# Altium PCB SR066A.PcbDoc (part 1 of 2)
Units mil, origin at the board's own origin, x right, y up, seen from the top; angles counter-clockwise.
Board outline 2000 x 2000 mil, 4 copper layers (Top Layer, Signal Layer 1, Signal Layer 2, Bottom Layer), stack 60.434 mil thick; 64 components, 14 nets, 91 pads, 124 vias.
Unrouted connection lines stored in the file: 2.
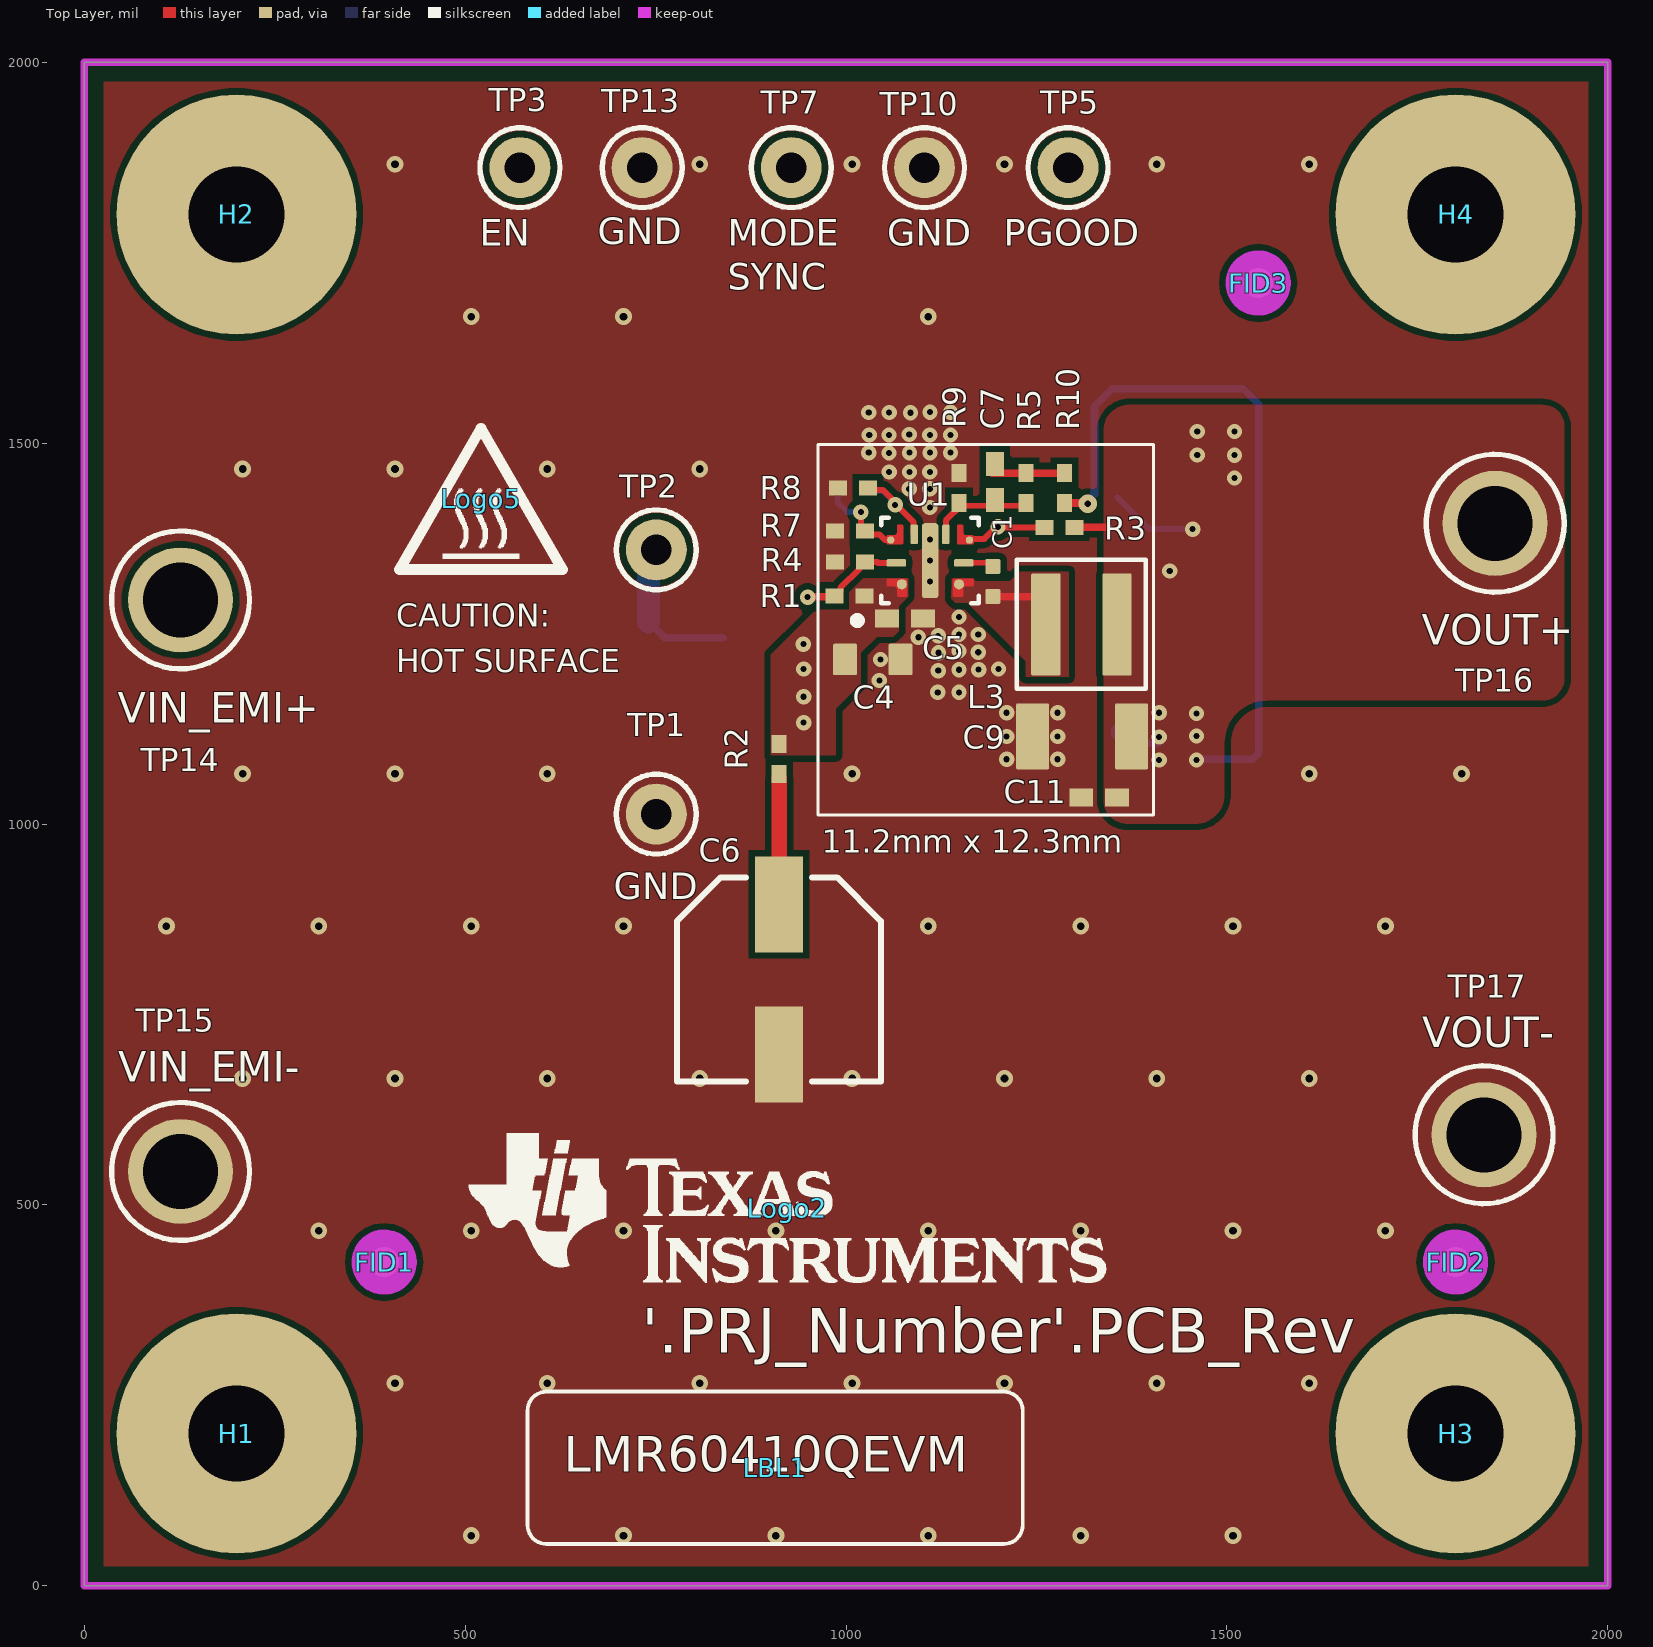
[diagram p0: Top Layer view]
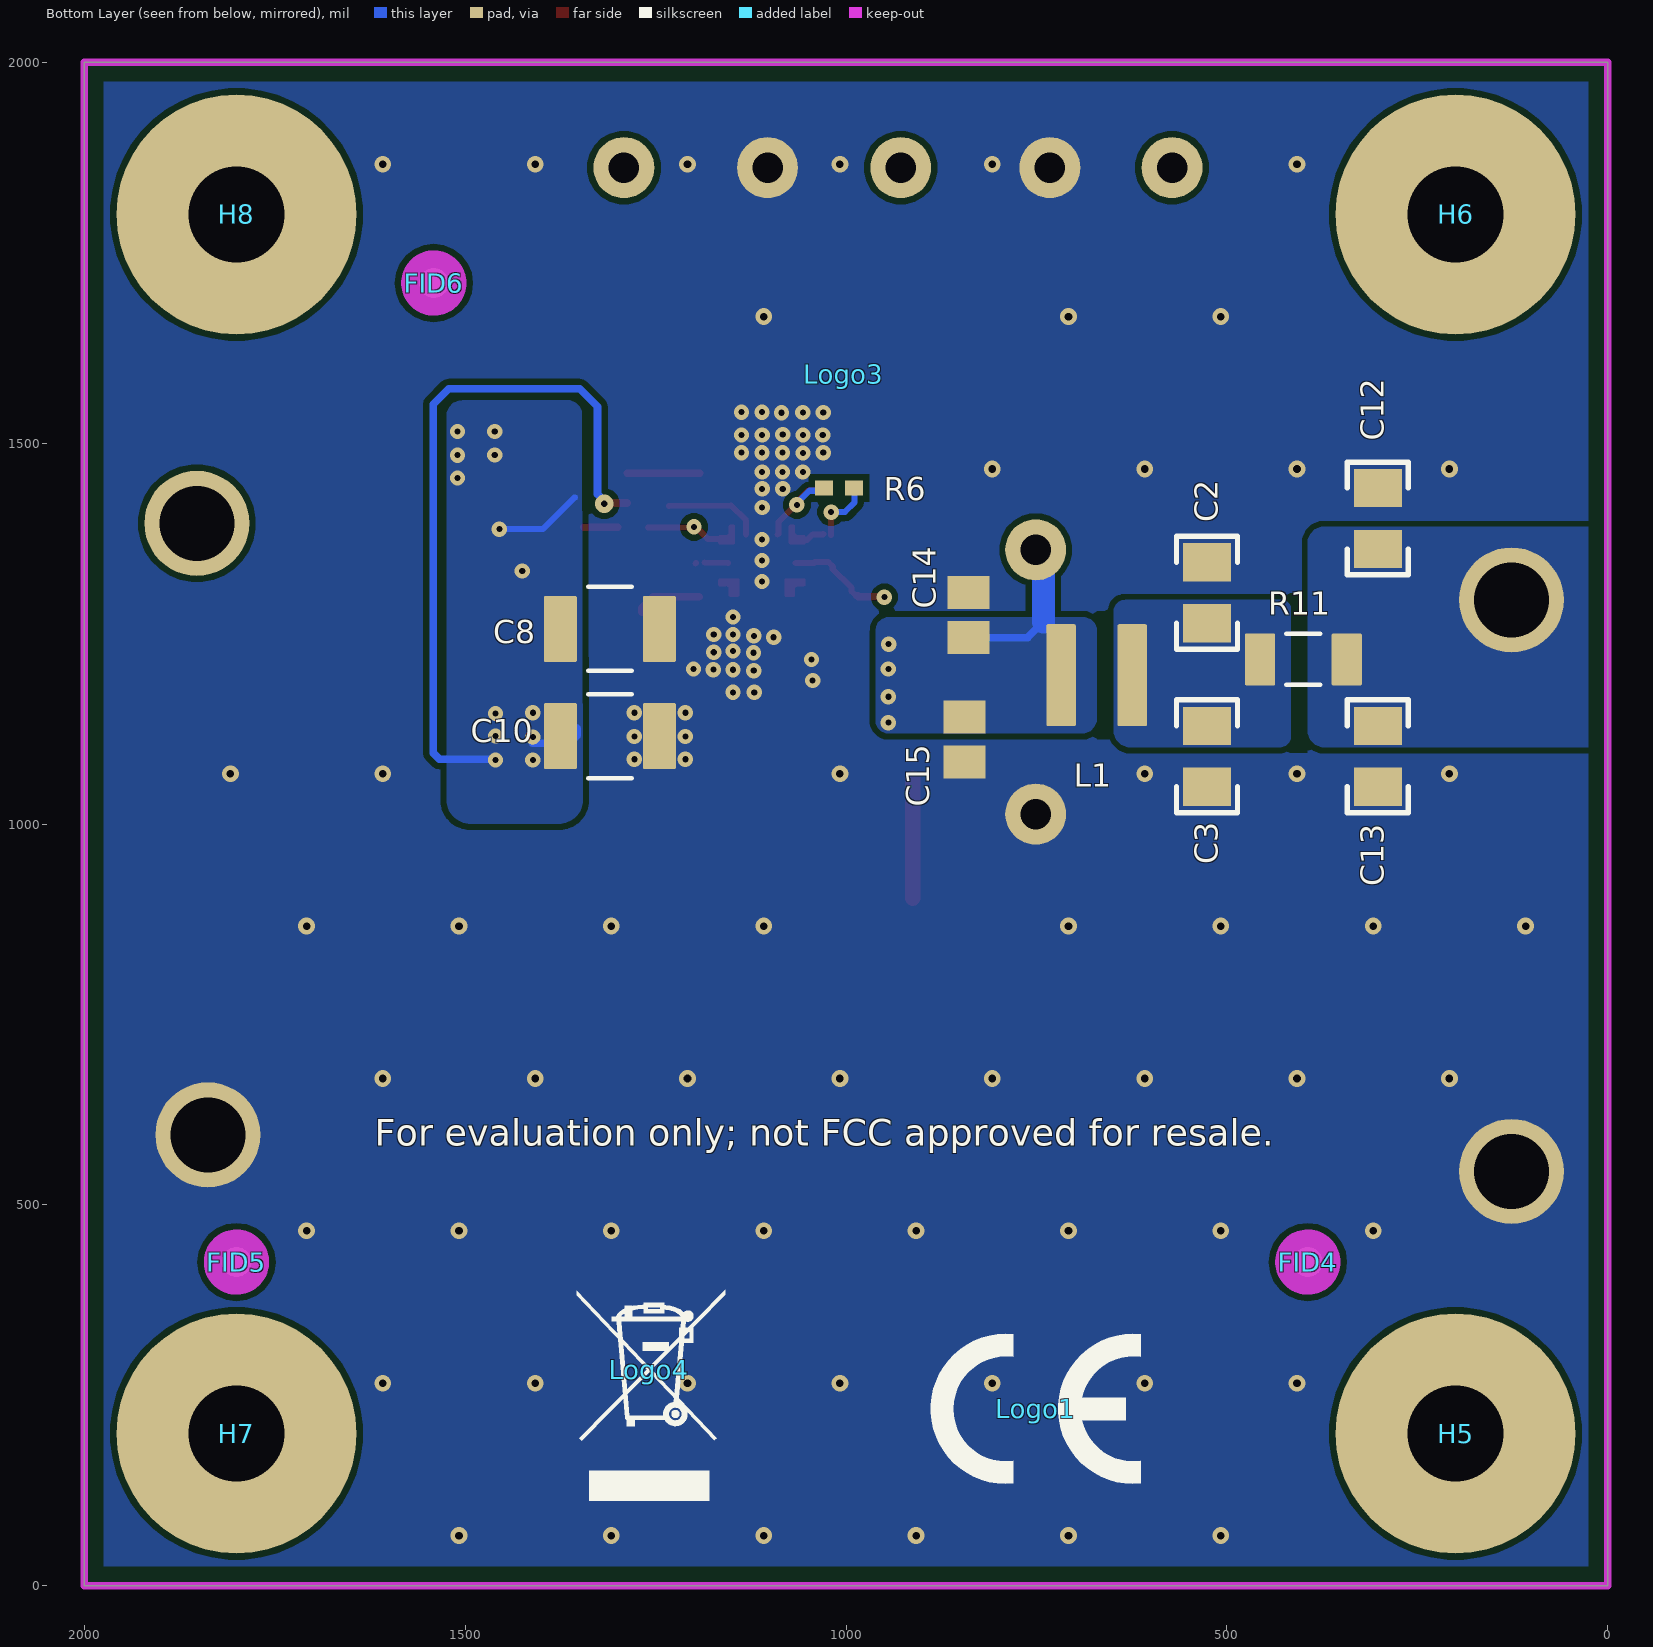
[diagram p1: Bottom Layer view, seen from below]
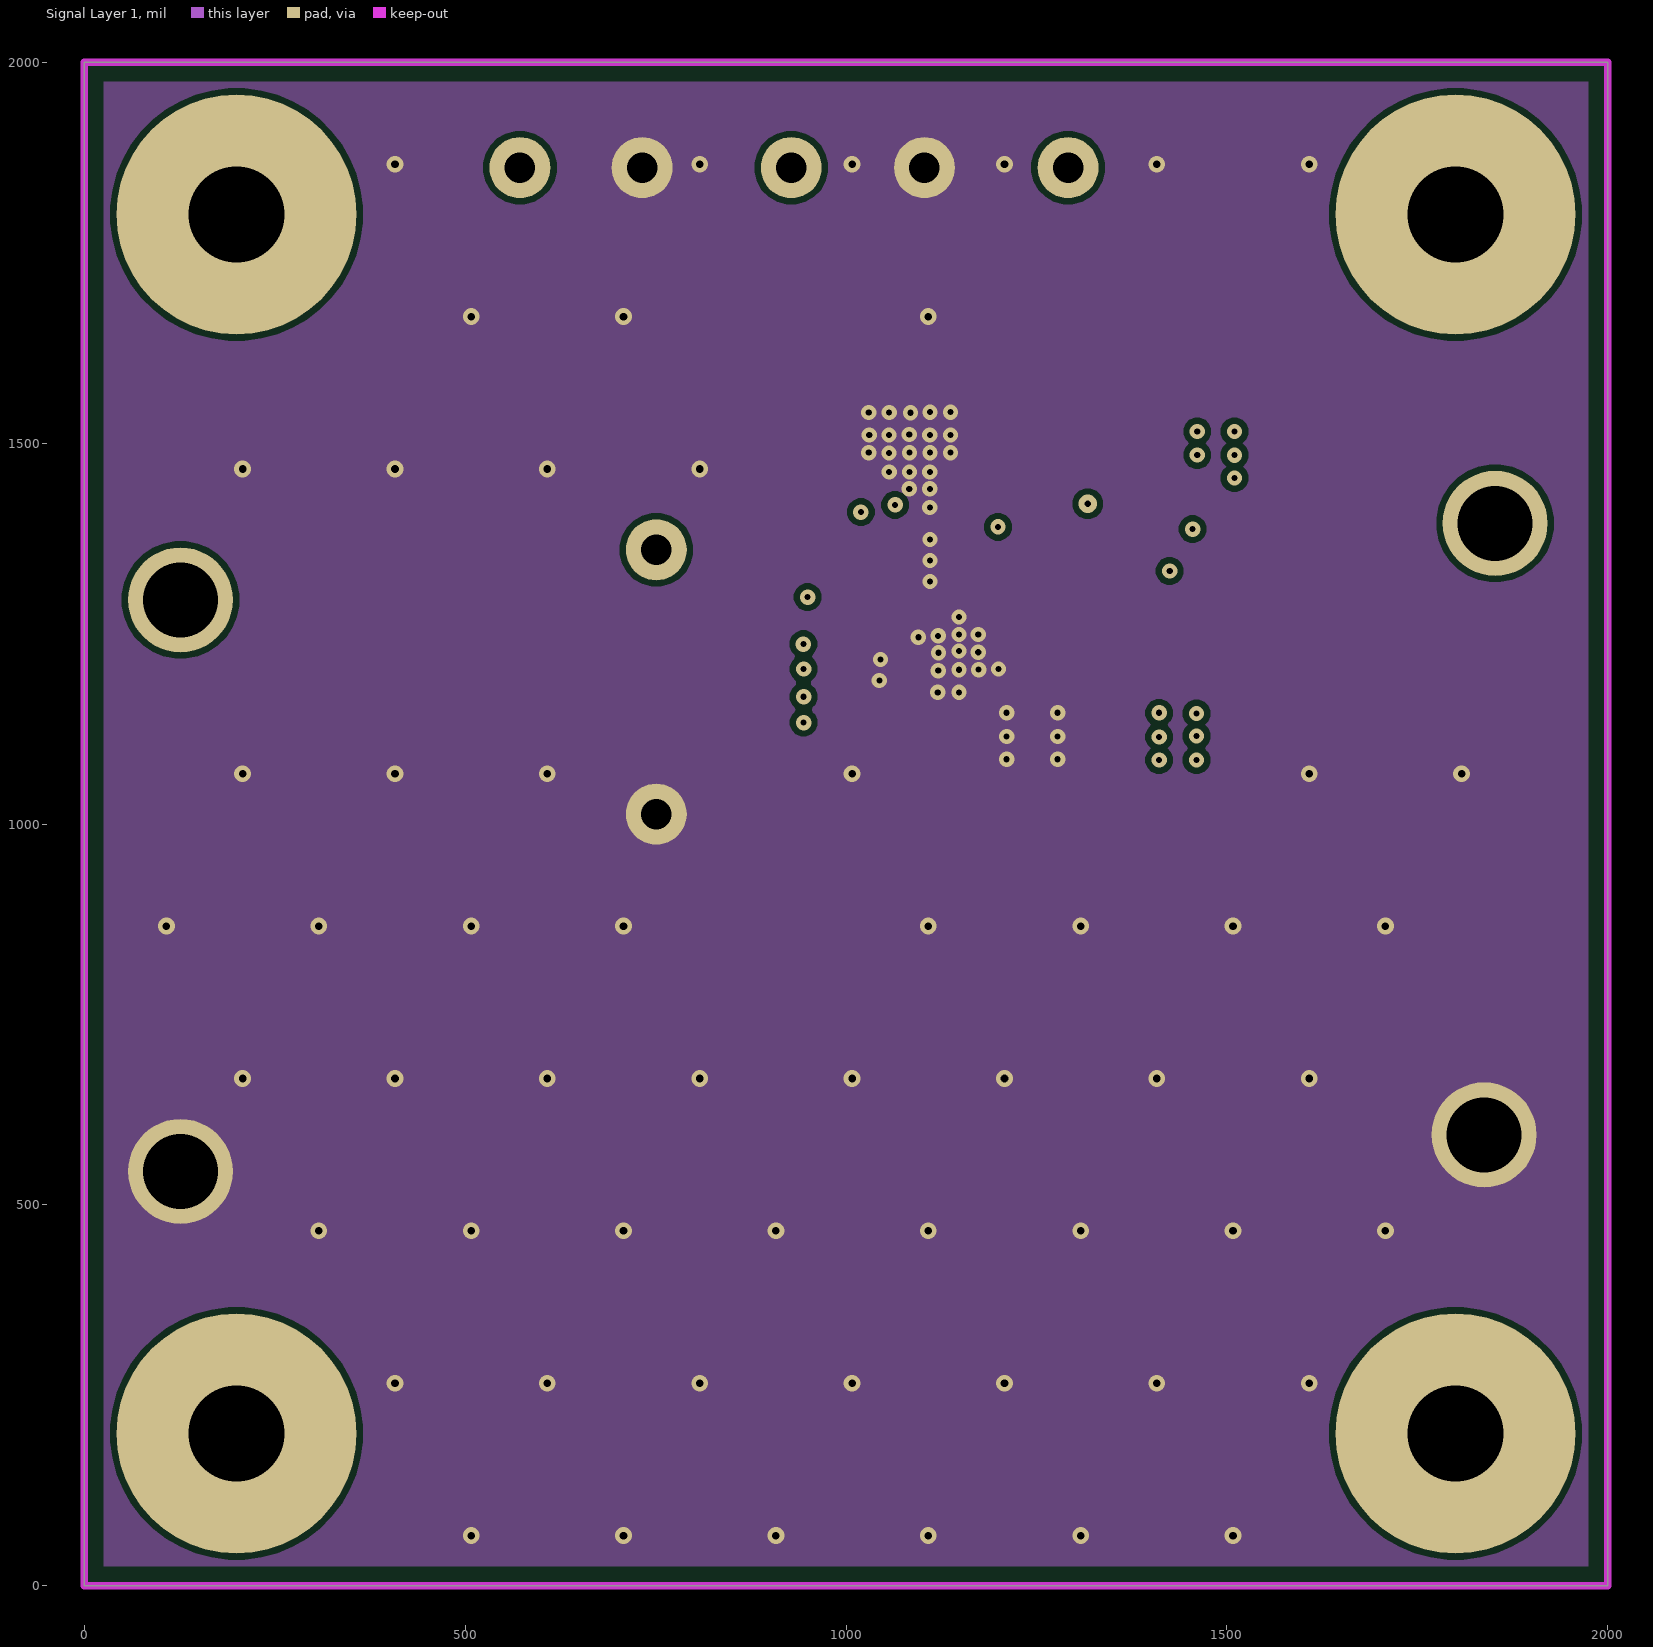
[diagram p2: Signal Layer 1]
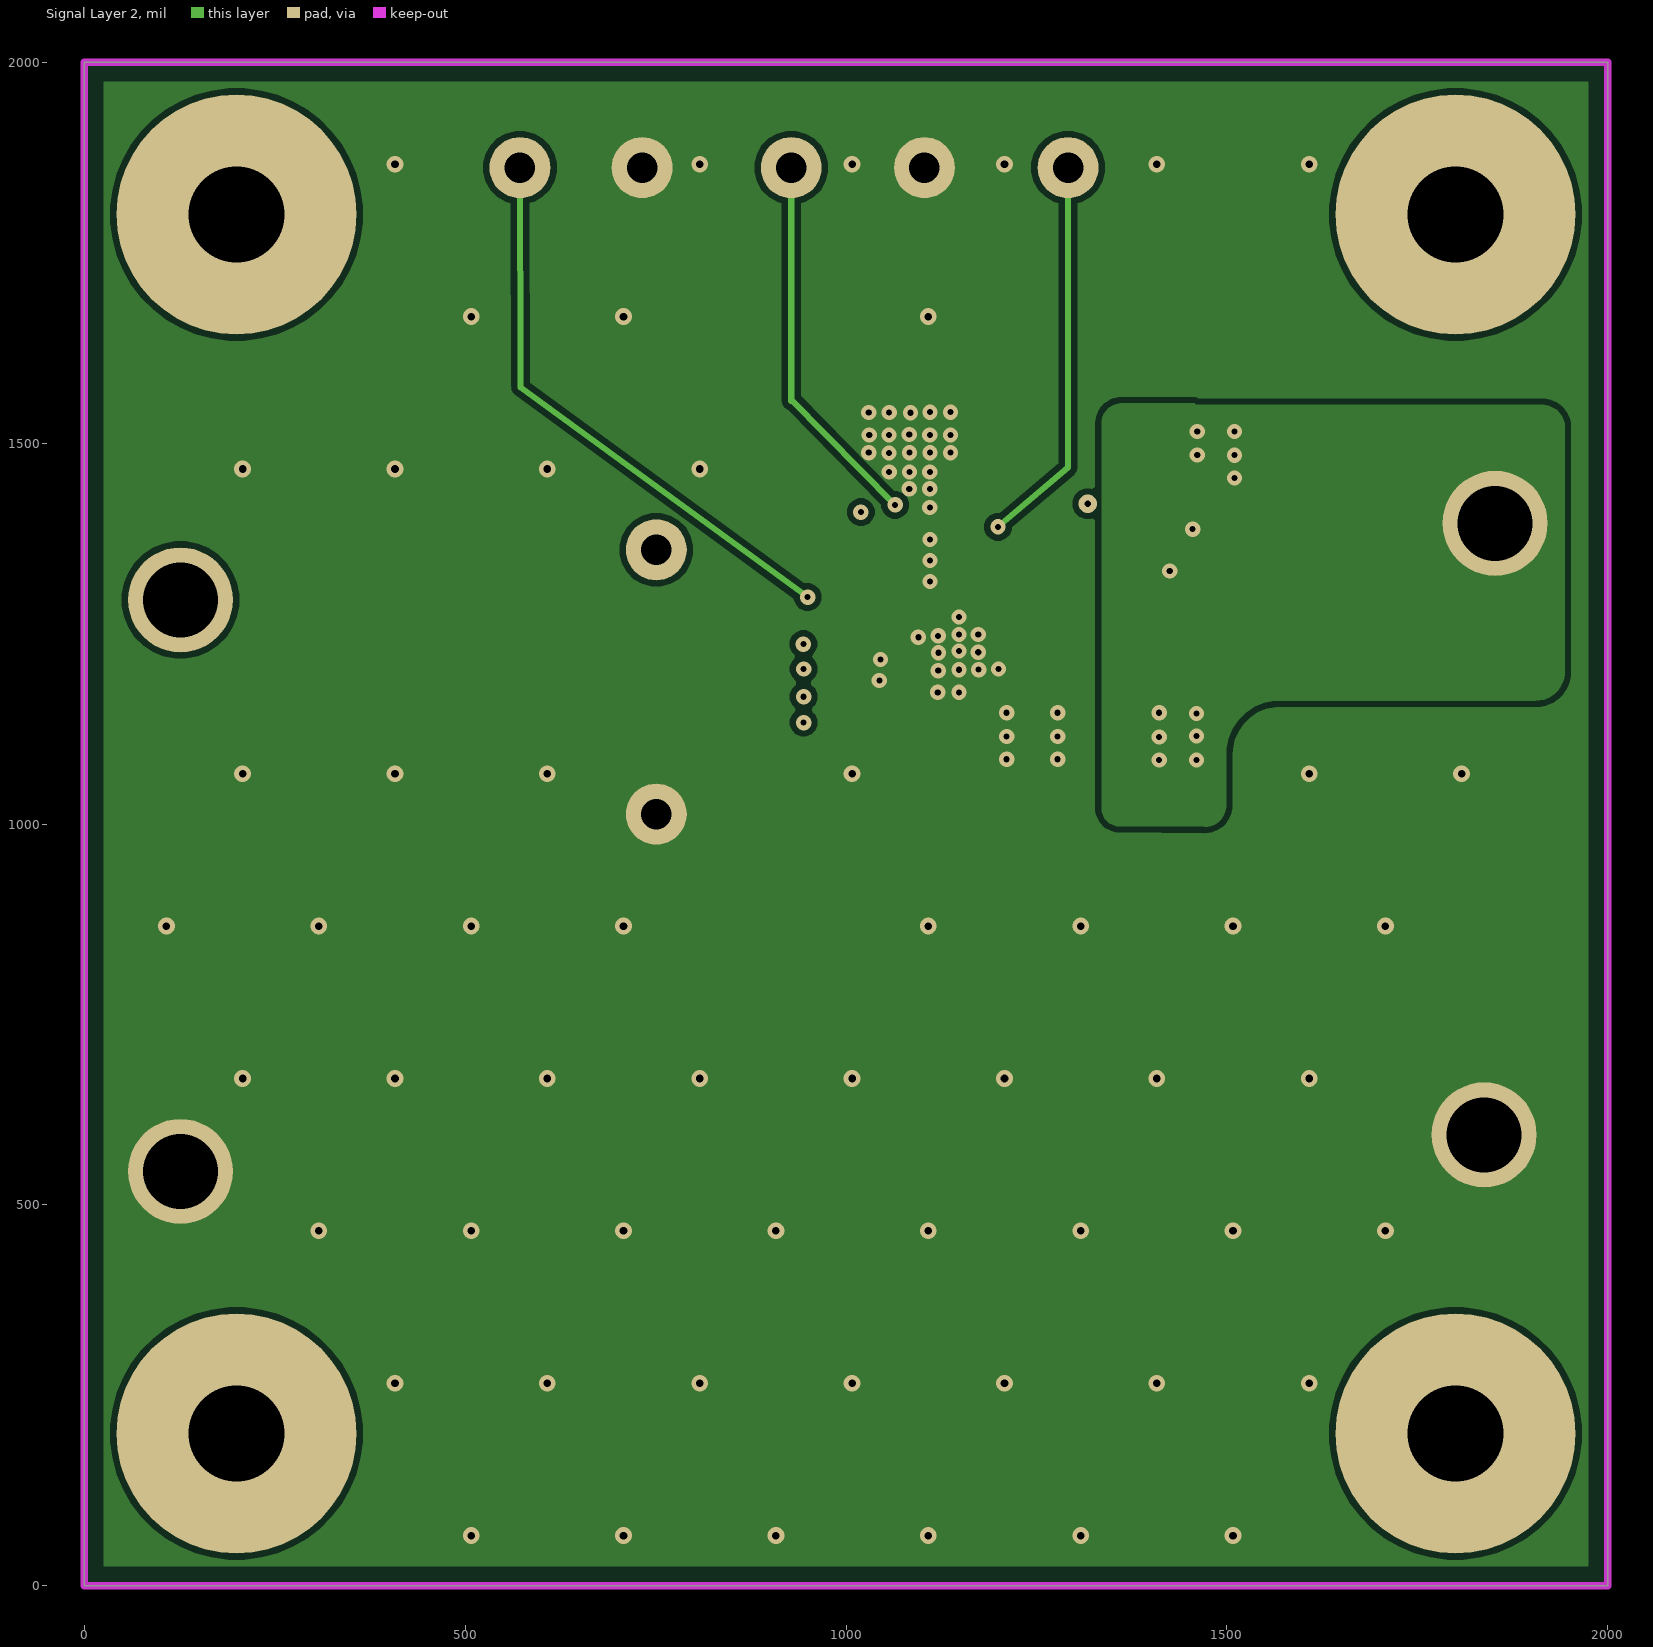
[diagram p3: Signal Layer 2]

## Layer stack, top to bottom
Top Solder: solder mask 0.4, Solder Resist, Dk 3.5
Top Layer: signal copper 2.8
Dielectric 1: core 10, FR-4 High Tg, Dk 4.2
Signal Layer 1: signal copper 1.417
Dielectric2: prepreg 32, FR-4 High Tg, Dk 4.2
Signal Layer 2: signal copper 1.417
Dielectric 3: core 10, FR-4 High Tg, Dk 4.2
Bottom Layer: signal copper 2.8
Bottom Solder: solder mask 0.4, Solder Resist, Dk 3.5

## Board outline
0,0 2000,0 2000,2000 0,2000

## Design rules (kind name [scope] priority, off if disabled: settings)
AcuteAngle [All] p1: minimum=4.50000000000000E+0001 checktracksonly=FALSE
AssemblyTestPointUsage [All] p1: valid=2
BoardOutlineClearance BoardOutlineClearance_MountingHoles [OnCopper and InComponentClass('Mounting Holes')] p1: gap=39.37 ignorepadtopadclearanceinfootprint=FALSE
BoardOutlineClearance BoardOutlineClearance_Poly [OnCopper and IsPoly] p2: gap=25 ignorepadtopadclearanceinfootprint=FALSE
BoardOutlineClearance [OnCopper and Not InComponentClass('Logo') and not InComponentClass('FiducialMark') and not InRegion(1000,500,4000,800) and not InPoly] p3: gap=50 ignorepadtopadclearanceinfootprint=FALSE
Clearance Clearance_Keepouts [((IsTrack Or IsArc) And Not InPoly) And IsFree and IsKeepOut vs ((IsTrack Or IsArc) And Not InPoly) And IsFree and IsKeepOut] p1: gap=0 ignorepadtopadclearanceinfootprint=FALSE
Clearance Clearance_Poly [InPolygon] p2: gap=8 ignorepadtopadclearanceinfootprint=TRUE
Clearance Clearance_FiducialMark [IsKeepOut and InComponentClass('FiducialMark') vs IsPad and InComponentClass('FiducialMark')] p3: gap=0 ignorepadtopadclearanceinfootprint=FALSE
Clearance Clearance_ModeSync [InNet('MODE/SYNC') And OnLayer('Top Layer') vs InNet('GND') And OnLayer('Top Layer')] p4: gap=4.9 ignorepadtopadclearanceinfootprint=FALSE
Clearance Clearance_FB [InNet('FB') And OnLayer('Top Layer') vs InNet('GND') And OnLayer('Top Layer')] p5: gap=4.9 ignorepadtopadclearanceinfootprint=FALSE
Clearance [All] p6: gap=7.9 ignorepadtopadclearanceinfootprint=TRUE except(5.9: SMDPad-Via)
ComponentClearance ComponentClearance_MountingHoles_FiducialMarks [InComponentClass('Mounting Holes') vs InComponentClass('FiducialMark')] p1: gap=50 collisioncheckmode=3 verticalgap=10 showdistances=FALSE
ComponentClearance ComponentClearance_Shunt [InComponentClass('Header') vs InComponentClass('Shunt')] p2: gap=0 collisioncheckmode=3 verticalgap=0 showdistances=FALSE
ComponentClearance ComponentClearance_Logo [InComponentClass('Logo')] p3: gap=50 collisioncheckmode=3 verticalgap=10 showdistances=FALSE
ComponentClearance ComponentClearance_ScrewToNut [(HasFootprint('NY PMS 440 0025 PH')) vs (HasFootprint('Keystone_1902C'))] p4: gap=5 collisioncheckmode=3 verticalgap=10 showdistances=FALSE
ComponentClearance ComponentClearance_MountingHoles [InComponentClass('Mounting Holes')] p5: gap=140 collisioncheckmode=3 verticalgap=100000 showdistances=FALSE
ComponentClearance ComponentClearance_SmallPassives [HasFootprint('0201*') or HasFootprint('0402*') or HasFootprint('0508') or HasFootprint('0603*') or HasFootprint('0612') or HasFootprint('0805*') or HasFootprint('0815*') or HasFootprint('0830*') or HasFootprint('1206*') or HasFootprint('1210*') or HasFootprint('1808*') or HasFootprint('1812*') or HasFootprint('1825*') or HasFootprint('2010*') or HasFootprint('2220*') or HasFootprint('2225*') or HasFootprint('2512*') or HasFootprint('2728*') or HasFootprint('3518*') vs HasFootprint('0201*') or HasFootprint('0402*') or HasFootprint('0508') or HasFootprint('0603*') or HasFootprint('0612') or HasFootprint('0805*') or HasFootprint('0815*') or HasFootprint('0830*') or HasFootprint('1206*') or HasFootprint('1210*') or HasFootprint('1808*') or HasFootprint('1812*') or HasFootprint('1825*') or HasFootprint('2010*') or HasFootprint('2220*') or HasFootprint('2225*') or HasFootprint('2512*') or HasFootprint('2728*') or HasFootprint('3518*')] p6: gap=14.96 collisioncheckmode=3 verticalgap=10 showdistances=FALSE
ComponentClearance ComponentClearance_THtoSMT [IsThruComponent vs IsSMTComponent] p7: gap=40 collisioncheckmode=3 verticalgap=30 showdistances=FALSE
ComponentClearance ComponentClearance_THtoTH [IsThruComponent vs IsThruComponent] p8: gap=30 collisioncheckmode=3 verticalgap=30 showdistances=FALSE
ComponentClearance ComponentClearance_L2 [HasFootprint('FP-XGL4030-222MEC_SMT_IND_4MM0_4MM0-MFG') vs HasFootprint('FP-XGL6060-822MEC_SMT_IND_6MM51_6MM71-MFG')] p9: gap=0 collisioncheckmode=3 verticalgap=0 showdistances=FALSE
ComponentClearance [All] p10: gap=14 collisioncheckmode=3 verticalgap=10 showdistances=FALSE
DiffPairsRouting [All] p1: maxlimit=100 minlimit=10 mostfreqgap=10 toplayer_minwidth=15 toplayer_maxwidth=15 toplayer_prefwidth=15 midlayer1_minwidth=15 midlayer1_maxwidth=15 midlayer1_prefwidth=15 midlayer2_minwidth=15 midlayer2_maxwidth=15 midlayer2_prefwidth=15 bottomlayer_minwidth=15 bottomlayer_maxwidth=15 bottomlayer_prefwidth=15 maxuncoupledlength=1000
FabricationTestPointUsage TestPointUsage [All] p1: valid=2 allowmultiple=FALSE
FabricationTestpoint Testpoint [All] p1: side=3 testpointundercomponent=TRUE minsize=40 maxsize=100 preferedsize=60 minholesize=0 maxholesize=40 preferedholesize=32 testpointgrid=1 allowsidetop=TRUE allowsidebottom=TRUE usegrid=TRUE gridtolerance=0.01
FanoutControl Fanout_LCC [IsLCC] p1: bgadir=Out bgaviamode=Centered fanoutstyle=Auto fanoutdirection=Alternating viagrid=1 // Fanout_LCC (Default Rule)
FanoutControl Fanout_BGA [IsBGA] p2: bgadir=Out bgaviamode=Centered fanoutstyle=Auto fanoutdirection=Alternating viagrid=1 // Fanout_BGA (Default Rule)
FanoutControl Fanout_Default [All] p4: bgadir=Out bgaviamode=Centered fanoutstyle=Auto fanoutdirection=Alternating viagrid=1 // Fanout_Default (Default Rule)
FanoutControl Fanout_Small [(CompPinCount < 5)] p5: bgadir=Out bgaviamode=Centered fanoutstyle=Auto fanoutdirection=OutThenIn viagrid=1 // Fanout_Small (Default Rule)
HoleSize [All] p1: absolutevalues=TRUE maxlimit=251 minlimit=7.87 maxpercent=80.000 minpercent=20.000
MinimumAnnularRing MinimumAnnularRing_ThermalPadVias [IsVia and InAnyComponent] p1: minimumring=5.91
MinimumAnnularRing [All] p2: minimumring=6
MinimumSolderMaskSliver MinimumSolderMaskSliver_Logo [InComponentClass('Logo') vs InComponentClass('Logo')] p1: minsoldermaskwidth=0.7
MinimumSolderMaskSliver [All] p2: minsoldermaskwidth=3.94
PlaneClearance [All] p1: clearance=9.84
PlaneConnect [All] p1: planeconnectstyle=Direct reliefexpansion=10 reliefentries=4 reliefconductorwidth=10 reliefairgap=10
PolygonConnect [All] p1: connectstyle=Direct reliefconductorwidth=10 reliefentries=4 polygonreliefangle="90 Angle" airgapwidth=10
RoutingVias ThermalPadVias [IsVia and InAnyComponent] p1: holewidth=7.87 width=19.68 viastyle="Through Hole" minholewidth=7.87 minwidth=19.68 maxholewidth=12.99 maxwidth=23.62
RoutingVias [All] p2: holewidth=8 width=20 viastyle="Through Hole" minholewidth=7.87 minwidth=19.68 maxholewidth=40 maxwidth=65
SilkToBoardRegionClearance [Not ((IsComment or IsDesignator) And (Hide <> 'False')) and not InRegion(1000,500,4000,800)] p1:
SilkToSilkClearance SilkToSilkClearance_Pb-FreeLogo [(HasFootprint('Pb-Free_Overlay_Medium') OR HasFootprint('Pb-Free_Overlay_Small')) vs (HasFootprint('Pb-Free_Overlay_Medium') OR HasFootprint('Pb-Free_Overlay_Small'))] p1: silktosilkclearance=0
SilkToSilkClearance [All] p2: silktosilkclearance=3.94
SilkToSolderMaskClearance SilkToComponentPadClearance [(IsPad or IsFill or IsRegion) and InAnycomponent] p1: minsilkscreentomaskgap=5 clearancetoexposedcopper=TRUE
SilkToSolderMaskClearance "Silk to Solder Mask Opening" [All] p2: minsilkscreentomaskgap=3.94 clearancetoexposedcopper=FALSE
SolderMaskExpansion [All] p1: expansion=1.97 istentingtop=FALSE
UnRoutedNet [All] p1: checkbadconnections=TRUE
Width [All] p1: maxlimit=100 minlimit=6 preferedwidth=10 checkconnectedcopper=TRUE
13 further rules are at their usual default settings.

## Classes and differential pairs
net class "EMI Class": NetC2_1 NetC12_1
component class SR066A_Schematic: C1 C2 C3 C4 C5 C6 C7 C8 C9 C10 C11 C12 C13 C14 C15 L1 L3 R1 R2 R3 R4 R5 R6 R7 R8 R9 R10 R11 TP1 TP2 TP3 TP5 TP7 TP10 TP13 TP14 TP15 TP16 TP17 U1
component class "Mounting Holes": H1 H2 H3 H4
component class Logo: Logo2
component class Label: LBL1
component class SR066A_Hardware: !PCB1 FID1 FID2 FID3 FID4 FID5 FID6 H1 H2 H3 H4 H5 H6 H7 H8 LBL1 Logo1 Logo2 Logo3 Logo4 Logo5 ZZ1 ZZ2 ZZ3 ZZ4
component class FiducialMark: FID1 FID2 FID3 FID4 FID5 FID6
component class AssemblyNote: ZZ1 ZZ2 ZZ3 ZZ4

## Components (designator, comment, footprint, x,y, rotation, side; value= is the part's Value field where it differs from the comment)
C1 "CS0402KRX7R8BB104" FP-CS0402KRX7R8BB104_0402-MFG 1192.85,1318.33 r270 top value=100nF
C2 "CGA4J3X7R1H225K125AB" 0805_HV 526.11,1303.53 r90 bottom value=2.2uF
C3 "CGA4J3X7R1H225K125AB" 0805_HV 526.11,1088.89 r270 bottom value=2.2uF
C4 "C2012X7R1H475K125AC" FP-C2012X7R1H475K125AC_0805-MFG 1035.24,1215.94 r180 top
C5 "GCM155R71H104KE02D" 0402 1077.42,1269.75 r0 top value=0.1uF
C6 "EEEFT1H470AP" Panasonic_D 911.95,796.17 r270 top value=47uF
C7 "CGA2B2C0G1H220J050BA" 0402 1195.29,1448.62 r270 top value=22pF
C8 "CGA6P1X7R1C226M250AC" FP-CGA6P1X7R1C226M250AC_1210-MFG 1309.97,1255.97 r0 bottom value=22µF
C9 "CGA6P1X7R1C226M250AC" FP-CGA6P1X7R1C226M250AC_1210-MFG 1309.9,1114.95 r0 top value=22µF
C10 "CGA6P1X7R1C226M250AC" FP-CGA6P1X7R1C226M250AC_1210-MFG 1309.9,1115.41 r0 bottom value=22µF
C11 "GCM155R71H104KE02D" 0402 1332.39,1035 r180 top value=0.1uF
C12 "CGA4J3X7R1H225K125AB" 0805_HV 302,1400.93 r90 bottom value=2.2uF
C13 "CGA4J3X7R1H225K125AB" 0805_HV 302,1088.89 r270 bottom value=2.2uF
C14 "CGA4J3X7R1H225K125AB" 0805L 839,1274 r90 bottom value=2.2uF
C15 "CGA4J3X7R1H225K125AB" 0805L 844.62,1111.08 r270 bottom value=2.2uF
FID1 "Fiducial" Fiducial10-20 393.92,425 r0 top
FID2 "Fiducial" Fiducial10-20 1800,425 r0 top
FID3 "Fiducial" Fiducial10-20 1541,1710 r0 top
FID4 "Fiducial" Fiducial10-20 393.92,425 r180 bottom
FID5 "Fiducial" Fiducial10-20 1800,425 r180 bottom
FID6 "Fiducial" Fiducial10-20 1541,1710 r180 bottom
H1 "NY PMS 440 0025 PH" "NY PMS 440 0025 PH" 200,200 r0 top
H2 "NY PMS 440 0025 PH" "NY PMS 440 0025 PH" 200,1800 r0 top
H3 "NY PMS 440 0025 PH" "NY PMS 440 0025 PH" 1800,200 r0 top
H4 "NY PMS 440 0025 PH" "NY PMS 440 0025 PH" 1800,1800 r0 top
H5 "1902C" Keystone_1902C 200,200 r180 bottom
H6 "1902C" Keystone_1902C 200,1800 r180 bottom
H7 "1902C" Keystone_1902C 1800,200 r180 bottom
H8 "1902C" Keystone_1902C 1800,1800 r180 bottom
L1 "XEL4020-222MEB" XEL4020 671,1195.27 r0 bottom value=2.2uH
L3 "XGL4030-562MEC" FP-XGL4030-562MEC_SMT_IND_4MM0_4MM0-MFG 1309,1262 r0 top value=5.6uH
LBL1 "THT-14-423-10" Label_650x200 907,155 r0 top
Logo1 "CE Mark" CE_Mark_5mm 751,232.35 r180 bottom
Logo2 "Texas Instruments" TI_Stacked_Overlay_Small 923,496 r0 top
Logo3 "FCC disclaimer" FCC_disclaimer 1003,1590 r180 bottom
Logo4 "WEEE logo" WEEE_Minimum 1258,284 r180 bottom
Logo5 "CAUTION HOT SURFACE" IEC_HotSurface_Small 521,1427 r0 top
R1 "CRCW040230K1FKED" 0402L 1004.46,1299.29 r0 top value=30.1k
R2 "RC0402JR-070RL" 0402L 912.28,1085.05 r90 top value=0
R3 "CRCW0402100KJNED" 0402L 1280,1389.41 r180 top value=100k
R4 "AC0402FR-0710KL" 0402L 1005.55,1343.89 r0 top value=10.0k
R5 "RC0402JR-070RL" 0402L 1236,1440.92 r90 top value=0
R6 "RC0402JR-070RL" 0402L 1009.26,1440.92 r0 bottom value=0
R7 "CRCW040215K0FKED" 0402L 1005.25,1384.37 r0 top value=15.0k
R8 "RC0402JR-070RL" 0402L 1009.26,1441.12 r0 top value=0
R9 "MCS0402MD1002BE100" 0402L 1148.42,1440.92 r270 top value=10.0k
R10 "RC0402JR-070RL" 0402L 1286.9,1440.92 r270 top value=0
R11 "5108" FP-5108_1206-MFG 399.69,1215.97 r0 bottom value=0
TP1 "5001" Keystone5001 751,1013 r90 top
TP2 "5000" Keystone5000 751,1359.84 r90 top
TP3 "5000" Keystone5000 572.05,1861.47 r180 top
TP5 "5002" Keystone5002 1291.44,1861.47 r0 top
TP7 "5004" Keystone5004 928.13,1861.47 r0 top
TP10 "5001" Keystone5001 1102.99,1861.47 r0 top
TP13 "5001" Keystone5001 732.44,1861.47 r0 top
TP14 "1502-2" Keystone1502-2 126.54,1294.12 r0 top
TP15 "1502-2" Keystone1502-2 126.54,544.05 r0 top
TP16 "1502-2" Keystone1502-2 1852,1394.69 r0 top
TP17 "1502-2" Keystone1502-2 1837.45,592.1 r0 top
U1 "LMR604103SRAKR" RAK0009A-MFG 1110.4,1345.61 r90 top
ZZ1 "This Assembly Note is for PCB labels only" AssemblyNoteLabel 93,2845 r0 top
ZZ2 "These assemblies are ESD sensitive, ESD precautions shall be observed." AssemblyNote 93,2732 r0 top
ZZ3 "These assemblies must be clean and free from flux and all contaminants. Use of no clean flux is not acceptable." AssemblyNote 94,2608 r0 top
ZZ4 "These assemblies must comply with workmanship standards IPC-A-610 Class 2, unless otherwise specified." AssemblyNote 89,2478 r0 top

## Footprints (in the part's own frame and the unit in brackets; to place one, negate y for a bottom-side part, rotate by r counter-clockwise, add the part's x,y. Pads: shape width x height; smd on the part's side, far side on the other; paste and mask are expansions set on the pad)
0402 [mm] "0402 from SM-752 data"
  rect 0.8x0.6 smd: 1(-0.6,0) 2(0.6,0)
  body extent -0.55,-0.3 0.55,0.3, height 0.6
0402L [mm] "0402 from SM-752 data"
  rect 0.6x0.5 smd: 1(-0.5,0) 2(0.5,0)
  body extent -0.55,-0.3 0.55,0.3, height 0.6
0805_HV [mil] "0805 with 30mil clearance between pads"
  rect 50x63 smd: 1(-40,0) 2(40,0)
  silkscreen extent -74,-40 74,40, body extent -43,-29 43,29, height 57
0805L [mm] "0805 from SM-752 data"
  rect 1.1x1.4 smd: 1(-0.75,0) 2(0.75,0)
  body extent -1.1,-0.72 1.1,0.72, height 1.45
AssemblyNote [mil] "Assembly Note"
AssemblyNoteLabel [mil] "Assembly Note for PCB Labels"
CE_Mark_5mm [mil] "Minimum text height for CE Mark"
  silkscreen extent -138,-98 138,98
FCC_disclaimer [mil]
Fiducial10-20 [mm]
  round 1 smd mask+0.5: 1(0,0)
  Top Layer keep-out circle w1.178: c0,0 r0.5
FP-5108_1206-MFG [mm]
  rrect10% 1.01x1.73 smd paste+0 mask+0: 1(-1.445,0) 2(1.445,0)
  silkscreen extent -0.57,-0.85 0.57,0.85, body extent -1.53,-0.85 1.53,0.85, height 0.71
FP-C2012X7R1H475K125AC_0805-MFG [mm]
  rrect13% 0.8x1.05 smd paste+0 mask+0: 1(-0.925,0) 2(0.925,0)
  body extent -1.43,-0.85 1.43,0.85, height 0.25
FP-CGA6P1X7R1C226M250AC_1210-MFG [mm]
  rrect9% 1.1x2.2 smd paste+0 mask+0: 1(-1.65,0) 2(1.65,0)
  silkscreen extent -0.72,-1.4 0.72,1.4, body extent -1.6,-1.25 1.6,1.25, height 2.81
FP-CS0402KRX7R8BB104_0402-MFG [mm]
  rrect20% 0.5x0.5 smd paste+0 mask+0: 1(-0.5,0) 2(0.5,0)
  body extent -0.87,-0.48 0.87,0.48, height 0.25
FP-XGL4030-562MEC_SMT_IND_4MM0_4MM0-MFG [mm]
  rrect10% 0.98x3.4 smd paste+0 mask+0: 1(-1.185,0) 2(1.185,0)
  silkscreen extent -2.15,-2.15 2.15,2.15, body extent -2.25,-2.25 2.25,2.25, height 0.25
IEC_HotSurface_Small [mil]
  silkscreen extent -107,-93 107,92
Keystone1502-2 [mm] "Double Turret"
  round 3.5 hole 2.5: 1(0,0)
  silkscreen extent -2.3,-2.3 2.3,2.3, body extent -1.6,-1.6 1.59,1.6, height 5.62
Keystone5000 [mil] "For Keystone 500x miniature loop terminals"
  round 80 hole 40: 1(0,0)
  silkscreen extent -52,-52 52,52, body extent -49,-49 49,49, height 182
Keystone5001 [mil] "For Keystone 500x miniature loop terminals"
  round 80 hole 40: 1(0,0)
  silkscreen extent -52,-52 52,52, body extent -49,-49 49,49, height 182
Keystone5002 [mil] "For Keystone 500x miniature loop terminals"
  round 80 hole 40: 1(0,0)
  silkscreen extent -52,-52 52,52, body extent -49,-49 49,49, height 182
Keystone5004 [mil] "For Keystone 500x miniature loop terminals"
  round 80 hole 40: 1(0,0)
  silkscreen extent -52,-52 52,52, body extent -49,-49 49,49, height 182
Keystone_1902C [mil] "Hex Standoff, 4-40 threaded, nylon"
  round 1 on Mech4: 0(0,0)
  body extent -145,-126 146,126, height 501
Label_650x200 [mil] "Thermal Transfer Label"
  round 1 on Mech13: 0(0,0)
  silkscreen extent -325,-100 325,100, body extent -325,-100 325,100, height 1
"NY PMS 440 0025 PH" [mm] "4-40 nylon screw and mounting hole"
  round 8 hole 3.2: 1(0,0)
  body extent -3.3,-3.3 3.3,3.3, height 2.69
Panasonic_D [mm] "SMD, 2-Leads, Dia 6.3mm"
  rect 3.2x1.6 smd: 1(-2.5,0) 2(2.5,0)
  silkscreen extent -3.4,-3.4 3.4,3.4, body extent -3.4,-3.4 3.4,3.4, height 6.11
RAK0009A-MFG [mm]
  round 0.337 smd paste-1000 mask+0: 1(-0.787,0.943) 3(-0.787,-0.962)
  rrect36% 2.5x0.55 smd paste-1000 mask-1000: 2(0,0)
  rrect40% 0.25x0.65 smd paste+0 mask+0: 4(-0.075,-1.125) 9(-0.075,1.125)
  round 0.247 smd paste+0 mask+0: 5(0.687,-1.312) 8(0.687,1.312)
  rrect40% 0.65x0.25 smd paste+0 mask+0: 6(0.875,-0.525) 7(0.875,0.525)
  Top Layer region: -1.15,0.755 -1.169,0.759 -1.185,0.77 -1.196,0.786 -1.2,0.805 -1.2,0.805 -1.2,1.05 -1.193,1.075 -1.175,1.093 -1.15,1.1 -1.15,1.1 -0.95,1.1 -0.912,1.108 -0.879,1.129 -0.858,1.162 -0.85,1.2 -0.85,1.2 -0.85,1.4 -0.843,1.425 -0.825,1.443 -0.8,1.45 -0.8,1.45 -0.65,1.45 -0.631,1.446 -0.615,1.435 -0.604,1.419 -0.6,1.4 -0.6,1.4 -0.6,0.805 -0.604,0.786 -0.615,0.77 -0.631,0.759 -0.65,0.755 -0.65,0.755
  Top Layer region: -1.15,-0.755 -1.169,-0.759 -1.185,-0.77 -1.196,-0.786 -1.2,-0.805 -1.2,-0.805 -1.2,-1.05 -1.196,-1.069 -1.185,-1.085 -1.169,-1.096 -1.15,-1.1 -1.15,-1.1 -0.95,-1.1 -0.912,-1.108 -0.879,-1.129 -0.858,-1.162 -0.85,-1.2 -0.85,-1.2 -0.85,-1.4 -0.846,-1.419 -0.835,-1.435 -0.819,-1.446 -0.8,-1.45 -0.8,-1.45 -0.65,-1.45 -0.631,-1.446 -0.615,-1.435 -0.604,-1.419 -0.6,-1.4 -0.6,-1.4 -0.6,-0.805 -0.604,-0.786 -0.615,-0.77 -0.631,-0.759 -0.65,-0.755 -0.65,-0.755
  Top Layer region: 1.15,-0.9 1.169,-0.904 1.185,-0.915 1.196,-0.931 1.2,-0.95 1.2,-0.95 1.2,-1.05 1.193,-1.075 1.175,-1.093 1.15,-1.1 1.15,-1.1 0.95,-1.1 0.912,-1.108 0.879,-1.129 0.858,-1.162 0.85,-1.2 0.85,-1.2 0.85,-1.4 0.843,-1.425 0.825,-1.443 0.8,-1.45 0.8,-1.45 0.6,-1.45 0.581,-1.446 0.565,-1.435 0.554,-1.419 0.55,-1.4 0.55,-1.4 0.55,-0.95 0.554,-0.931 0.565,-0.915 0.581,-0.904 0.6,-0.9 0.6,-0.9
  Top Layer region: 1.15,0.9 1.169,0.904 1.185,0.915 1.196,0.931 1.2,0.95 1.2,0.95 1.2,1.05 1.196,1.069 1.185,1.085 1.169,1.096 1.15,1.1 1.15,1.1 0.95,1.1 0.912,1.108 0.879,1.129 0.858,1.162 0.85,1.2 0.85,1.2 0.85,1.4 0.846,1.419 0.835,1.435 0.819,1.446 0.8,1.45 0.8,1.45 0.6,1.45 0.581,1.446 0.565,1.435 0.554,1.419 0.55,1.4 0.55,1.4 0.55,0.95 0.554,0.931 0.565,0.915 0.581,0.904 0.6,0.9 0.6,0.9
  silkscreen extent -2.12,-1.63 1.43,2.55, body extent -1.35,-1.55 1.35,1.55, height 0.25
TI_Stacked_Overlay_Small [mil]
  silkscreen extent -418,-98 418,98
WEEE_Minimum [mil] "WEEElie bin"
  silkscreen extent -95,-172 99,104
XEL4020 [mm] "SMD, 2-Leads, Body 4x4mm, Pitch 2.37mm"
  rrect10% 0.98x3.4 smd: 1(-1.185,0) 2(1.185,0)
  body extent -2.15,-2.15 2.15,2.15, height 2.1

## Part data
C1: library part CMP-0050130-1, "0.1 µF ±10% 25V Ceramic Capacitor X7R 0402 (1005 Metric)", Digikey Part Number=13-CS0402KRX7R8BB104CT-ND, Manufacturer=Yageo, Mouser Part Number=603-CS0402KRX78BB104, Operating Temperature Range="-55°C to +125°C", TempCo=15%, Temperature Characteristic=X7R, Tolerance_%=10%, ValueDisplayed=100nF
C2 C3 C12 C13 C14 C15: library part CMP-0007977-2, "CAP, CERM, 2.2 uF, 50 V, +/- 10%, X7R, AEC-Q200 Grade 1, 0805", Cap_Case=0805, Manufacturer=TDK, Supplier Part Number 1=445-174216-1-ND, TempCo=X7R, Tolerance_%=10%, Value1="0.003288 ohm", Value2=50V, ValueDisplayed=2.2uF
C4: library part CMP-0088943-1, "4.7µF ±10% 50V Ceramic Capacitor X7R 0805 (2012 Metric)", Digikey Part Number=445-C2012X7R1H475K125ACCT-ND, Manufacturer=TDK, Mouser Part Number=810-C2012X7R475K125C, Operating Temperature Range="-55°C to +125°C", TempCo=15%, Temperature Characteristic=X7R, Tolerance_%=10%, ValueDisplayed=4.7uF
C5 C11: library part CMP-0006356-2, "CAP, CERM, 0.1 uF, 50 V, +/- 10%, X7R, AEC-Q200 Grade 1, 0402", Cap_Case=0402, Manufacturer=MuRata, Supplier Part Number 1=490-10672-1-ND, TempCo=X7R, Tolerance_%=10%, Value1=Unknown, Value2=50V, ValueDisplayed=0.1uF
C6: library part CMP-0011204-2, "CAP, AL, 47 uF, 50 V, +/- 20%, 0.68 ohm, AEC-Q200 Grade 2, SMD", Cap_Case=6.3x5.8mm, Manufacturer=Panasonic, Supplier Part Number 1=PCE5023CT-ND, Tolerance_%=20%, Value1="0.68 ohm", Value2=50V, ValueDisplayed=47uF
C7: library part CMP-0860831-1, "CAP, CERM, 22 pF, 50 V,+/- 5%, C0G/NP0, AEC-Q200 Grade 1, 0402", Cap_Case=0402, Manufacturer=TDK, TempCo=C0G/NP0, Tolerance_%=5%, Value2=50V, ValueDisplayed=22pF
C8 C9 C10: library part CMP-0043794-1, "Cap Ceramic 22uF 16V X7R 20% Pad SMD 1210 +125°C Automotive T/R", Manufacturer=TDK, Operating Temperature Range="-55°C to +125°C", TempCo=15%, Temperature Characteristic=X7R, Tolerance_%=0.2%, ValueDisplayed=22uF
FID1 FID2 FID3 FID4 FID5 FID6: library part CMP-0077181-1, "Fiducial mark.  There is nothing to buy or mount.", Manufacturer=N/A
H1 H2 H3 H4: library part CMP-0003617-1, "Machine Screw, Round, #4-40 x 1/4, Nylon, Philips panhead", Manufacturer="B&F Fastener Supply", Supplier Part Number 1=H542-ND
H5 H6 H7 H8: library part CMP-0003610-1, "Standoff, Hex, 0.5\"L #4-40 Nylon", Manufacturer=Keystone, Supplier Part Number 1=36-1902C-ND
L1: library part CMP-0061079-2, "Inductor, Shielded, Composite, 2.2 uH, 5.5 A, 0.0362 ohm, AEC-Q200 Grade 1, SMD", Manufacturer=Coilcraft, Value1="0.0362 ohm", Value2=5.5A, ValueDisplayed=2.2uH
L3: library part CMP-0120190-1, "5.6 µH Shielded Molded Inductor 5.5 A 34.7mOhm Max 1616 (4040 Metric)", Digikey Part Number=2457-XGL4030-562MEC-ND, Manufacturer=Coilcraft, Operating Temperature Range=to, Self Resonant Frequency=25MHz, Test Frequency=1MHz, Tolerance_%=20%
LBL1: library part CMP-0003625-1, "Thermal Transfer Printable Labels, 0.650\" W x 0.200\" H - 10,000 per roll", Manufacturer=Brady, Supplier Part Number 1=97C5133
Logo1: library part CMP-0074844-2, Manufacturer="Texas Instruments"
Logo2: library part CMP-0074838-1, "Texas Instrument Corporate Signature"
Logo3: library part CMP-0074847-1, "FCC_disclaimer"
Logo4: library part CMP-0074769-4, Manufacturer="Texas Instruments"
Logo5: library part CMP-0074837-2, "IEC 61010-1 Hot Surface Warning", Manufacturer="Texas Instruments"
R1: library part CMP-0026284-2, "RES, 30.1 k, 1%, 0.063 W, AEC-Q200 Grade 0, 0402", Manufacturer=Vishay-Dale, Power_W=63mW, Supplier Part Number 1=541-30.1KLCT-ND, TempCo="100 ppm/C", Tolerance_%=1%, Value2=0.063W, Value_Code=30k1, ValueDisplayed=30.1k
R2 R5 R6 R8 R10: library part CMP-0027004-2, "RES, 0, 5%, 0.063 W, 0402", Manufacturer="Yageo America", Power_W=63mW, Supplier Part Number 1=311-0.0JRCT-ND, TempCo="200 ppm/C", Tolerance_%=5%, Value2=0.063W, Value_Code=0000, ValueDisplayed=0
R3: library part CMP-0026823-3, "RES, 100 k, 5%, 0.063 W, AEC-Q200 Grade 0, 0402", Manufacturer=Vishay-Dale, Power_W=63mW, Supplier Part Number 1=541-100KJCT-ND, TempCo="200 ppm/C", Tolerance_%=5%, Value2=0.063W, Value_Code=100k
R4: library part CMP-0077731-1, "RES, 10.0 k, 1%, 0.063 W, AEC-Q200 Grade 0, 0402", Manufacturer="Yageo America", Power_W=63mW, Supplier Part Number 1=YAG3436CT-ND, TempCo="100 ppm/C", Tolerance_%=1%, Value2=0.063W, Value_Code=10k0, ValueDisplayed=10.0k
R7: library part CMP-0026027-3, "RES, 15.0 k, 1%, 0.063 W, AEC-Q200 Grade 0, 0402", Manufacturer=Vishay-Dale, Power_W=63mW, Supplier Part Number 1=541-15.0KLCT-ND, TempCo="100 ppm/C", Tolerance_%=1%, Value2=0.063W, Value_Code=15k0, ValueDisplayed=15.0k
R9: library part CMP-0077124-1, "RES, 10.0 k, 0.1%, 0.1 W, AEC-Q200 Grade 0, 0402", Manufacturer=Vishay/Beyschlag, Power_W=100mW, Supplier Part Number 1=MCS0402-10.0K-MBCT-ND, TempCo="25 ppm/C", Tolerance_%=0.1%, Value2=0.1W, Value_Code=10k0, ValueDisplayed=10.0k
R11: library part CMP-0122408-1, "0 Ohms Jumper 0.5W, 1/2W Chip Resistor 1206 (3216 Metric) - Metal Element", Digikey Part Number=36-5108CT-ND, Manufacturer=Keystone, Mouser Part Number=534-5108, Operating Temperature Range=to, Power_W=500mW
TP1 TP10 TP13: library part CMP-0055138-2, "Test Point, Miniature, Black, TH", Color=Black, Manufacturer="Keystone Electronics", Supplier Part Number 1=36-5001-ND
TP2 TP3: library part CMP-0055137-2, "Test Point, Miniature, Red, TH", Color=Red, Manufacturer="Keystone Electronics", Supplier Part Number 1=36-5000-ND
TP5: library part CMP-0055139-2, "Test Point, Miniature, White, TH", Color=White, Manufacturer="Keystone Electronics", Supplier Part Number 1=36-5002-ND
TP7: library part CMP-0055141-2, "Test Point, Miniature, Yellow, TH", Color=Yellow, Manufacturer="Keystone Electronics", Supplier Part Number 1=36-5004-ND
TP14 TP15 TP16 TP17: library part CMP-0055113-1, "Terminal, Turret, TH, Double", Manufacturer=Keystone, Supplier Part Number 1=36-1502-2-ND
U1: library part CMP-0123705-1, Manufacturer="Texas Instruments", Operating Temperature Range=to
ZZ1: library part CMP-0003616-3
ZZ2: library part CMP-0077236-1
ZZ3: library part CMP-0077237-1
ZZ4: library part CMP-0077238-1

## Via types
v1: diameter 20, hole 8, Top Layer to Bottom Layer, tented both sides, 64 vias
v2: diameter 22, hole 10, Top Layer to Bottom Layer, tented both sides, 56 vias
v3: diameter 19.68, hole 7.87, Top Layer to Bottom Layer, tented both sides, 3 vias
v4: diameter 24, hole 8, Top Layer to Bottom Layer, tented both sides, 1 vias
